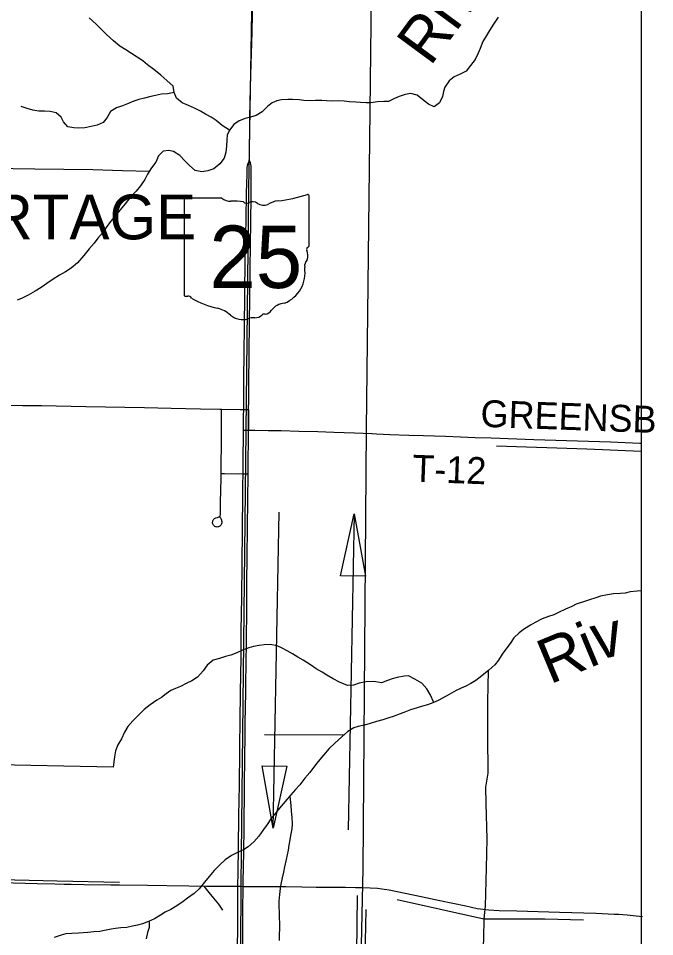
# Model space of a CAD drawing. Extents: x 0 to 680, y 0 to 834.
# Drawn here: x 324.2 to 375.8, y 148.8 to 223.2 of the extents above; entities that cross this region are included whole.
import ezdxf

# ---------------------------------------------------------------- set-up
doc = ezdxf.new("R2010")
doc.units = 0
for name, color, linetype in [('GM_X_Corporation_Text', 7, 'Continuous'), ('GM_X_County_Road', 7, 'Continuous'), ('GM_X_Interstate_Route', 7, 'Continuous'), ('GM_X_Major_River', 7, 'Continuous'), ('GM_X_Minor_River', 7, 'Continuous'), ('GM_X_Minor_River_Text', 7, 'Continuous'), ('GM_X_Rail_Line', 7, 'Continuous'), ('GM_X_State_Location', 7, 'Continuous'), ('GM_X_State_Route', 7, 'Continuous'), ('GM_X_State_Shield', 7, 'Continuous'), ('GM_X_Township_Road', 7, 'Continuous'), ('GM_X_Township_Road_Text', 7, 'Continuous'), ('SH_Text', 7, 'Continuous')]:
    doc.layers.add(name, color=color, linetype=linetype)

msp = doc.modelspace()

# ---------------------------------------------------------------- linework, layer by layer
at = {"layer": 'GM_X_County_Road'}
for p, q in [((342.032, 152.832), (342.242, 152.831)), ((342.242, 152.831), (342.455, 152.828))]:
    msp.add_line(p, q, dxfattribs=at)
for points in [[(310.737, 153.565), (311.451, 153.537), (318.25, 153.307), (319.084, 153.267), (320.873, 153.221), (322.543, 153.165), (323.855, 153.121), (324.809, 153.093), (325.764, 153.069), (327.195, 153.029), (327.935, 153.016), (328.508, 153.006), (329.581, 152.976), (331.728, 152.957), (332.444, 152.957), (334.712, 152.923), (336.263, 152.896), (338.053, 152.879), (339.485, 152.854), (341.274, 152.836), (342.032, 152.832)], [(342.455, 152.828), (343.392, 152.815), (344.704, 152.809), (345.897, 152.808), (347.197, 152.787), (348.37, 152.763), (349.548, 152.761), (350.502, 152.763), (350.74, 152.756), (351.56, 152.745), (351.679, 152.748), (352.152, 152.74), (352.749, 152.72), (353.346, 152.679), (353.703, 152.636), (354.293, 152.534), (356.865, 151.999), (358.382, 151.677), (360.486, 151.236), (361.42, 151.042), (361.889, 150.966), (362.362, 150.917), (363.195, 150.872), (364.626, 150.836), (368.087, 150.74), (371.07, 150.644), (372.517, 150.585)], [(372.517, 150.585), (372.86, 150.571), (373.576, 150.524), (374.051, 150.474), (374.822, 150.37)]]:
    msp.add_lwpolyline(points, dxfattribs=at)
at = {"layer": 'GM_X_Interstate_Route'}
msp.add_lwpolyline([(44.693, 394.069), (374.693, 394.069), (374.693, 64.069), (44.693, 64.069)], close=True, dxfattribs=at)
at = {"layer": 'GM_X_Major_River'}
for points in [[(363.105, 223.315), (362.739, 222.762), (362.402, 222.238), (362.167, 221.83), (361.874, 221.335), (361.669, 220.767), (361.507, 220.388), (361.243, 219.893), (360.863, 219.398), (360.512, 218.933), (360.03, 218.686), (359.563, 218.483)], [(359.563, 218.483), (359.14, 218.149), (358.803, 217.654), (358.685, 217.29), (358.597, 216.896), (358.362, 216.386), (357.938, 216.052), (357.458, 216.272), (356.993, 216.638), (356.543, 216.99), (356.048, 217.123), (355.581, 217.036), (355.1, 216.877), (354.721, 216.718), (354.224, 216.486), (353.86, 216.473), (353.336, 216.46), (352.796, 216.374), (352.432, 216.36), (351.966, 216.391), (351.587, 216.436), (351.077, 216.466), (350.64, 216.511), (350.189, 216.542), (349.722, 216.514), (349.213, 216.545), (348.819, 216.561), (348.309, 216.562), (347.93, 216.549), (347.377, 216.55), (346.984, 216.61), (346.459, 216.655), (346.08, 216.656), (345.57, 216.628), (345.177, 216.528), (344.812, 216.368), (344.447, 216.092), (343.994, 215.641), (343.512, 215.351), (343.045, 215.207), (342.622, 215.106), (342.141, 214.918), (341.703, 214.627), (341.337, 214.162), (341.161, 213.739), (341.116, 213.375), (341.1, 212.864), (341.055, 212.383), (340.922, 211.888), (340.571, 211.422), (340.089, 211.015), (339.593, 210.856), (339.097, 210.785), (338.573, 210.888), (338.108, 211.283), (337.76, 211.649), (337.309, 212.102), (336.8, 212.425), (336.436, 212.499), (335.97, 212.442), (335.605, 212.064), (335.384, 211.554), (335.033, 211.103), (334.697, 210.593), (334.477, 210.142), (334.14, 209.647), (333.774, 209.196), (333.277, 208.673), (332.882, 208.192), (332.487, 207.698), (332.107, 207.232), (331.712, 206.752), (331.361, 206.272), (331.097, 205.893), (330.688, 205.399), (330.366, 204.991), (329.971, 204.526), (329.532, 204.002), (329.021, 203.406), (328.524, 202.955), (328.057, 202.679), (327.575, 202.389), (327.049, 202.07), (326.553, 201.721), (326.086, 201.402), (325.604, 201.111), (325.02, 200.778), (324.495, 200.502), (324.13, 200.357)], [(374.693, 176.786), (374.377, 176.759), (373.823, 176.702), (373.4, 176.601), (373.022, 176.588), (372.468, 176.546), (371.987, 176.474), (371.404, 176.359), (371.039, 176.229), (370.529, 176.07), (370.033, 175.911), (369.449, 175.708), (369.084, 175.535), (368.574, 175.303), (368.005, 175.042), (367.64, 174.853), (367.202, 174.709), (366.692, 174.521), (366.123, 174.23), (365.743, 174.013), (365.261, 173.723), (364.823, 173.388), (364.399, 172.981), (364.092, 172.53), (363.741, 172.064), (363.448, 171.657), (363.155, 171.176), (362.848, 170.783), (362.366, 170.362), (361.796, 169.911), (361.3, 169.534), (360.891, 169.272), (360.497, 169.069), (360.118, 168.895), (359.709, 168.707), (359.14, 168.388), (358.614, 168.083), (358.25, 167.909), (357.826, 167.706), (357.389, 167.547), (356.981, 167.431), (356.543, 167.301), (356.003, 167.142), (355.478, 166.94), (355.099, 166.795), (354.676, 166.636), (354.166, 166.462), (353.772, 166.332), (353.261, 166.188), (352.751, 166.029), (352.284, 165.914), (351.774, 165.798), (351.41, 165.683), (350.928, 165.378), (350.46, 164.956), (349.89, 164.447), (349.423, 163.997), (348.955, 163.473), (348.531, 162.964), (348.238, 162.585), (347.843, 162.061), (347.448, 161.61), (347.039, 161.072)], [(347.039, 161.072), (346.688, 160.693), (346.322, 160.242), (345.869, 159.704), (345.401, 159.166), (345.109, 158.787), (344.684, 158.293), (344.392, 157.856), (344.114, 157.448), (343.719, 156.895), (343.324, 156.429), (342.856, 156.022), (342.491, 155.79), (342.039, 155.602), (341.514, 155.326), (341.003, 154.978), (340.55, 154.57), (340.111, 154.105), (339.702, 153.639), (339.307, 153.159), (338.883, 152.635), (338.488, 152.257), (337.948, 151.865), (337.583, 151.589), (337.087, 151.255), (336.59, 150.95), (336.123, 150.732), (335.759, 150.485), (335.262, 150.181), (334.781, 149.978), (334.299, 149.789), (333.877, 149.674), (333.483, 149.588), (333.031, 149.501), (332.55, 149.474), (332.113, 149.417), (331.749, 149.359), (331.209, 149.244), (330.845, 149.172), (330.364, 149.13), (329.868, 149.088), (329.475, 149.06), (329.096, 149.032), (328.557, 149.004), (328.076, 148.976), (327.697, 148.875), (327.143, 148.687)]]:
    msp.add_lwpolyline(points, dxfattribs=at)
at = {"layer": 'GM_X_Minor_River'}
for points in [[(245.729, 222.703), (245.676, 219.669), (245.678, 215.687), (245.626, 213.106), (247.214, 213.072), (253.915, 212.95), (258.548, 212.805), (262.03, 212.707), (264.535, 212.583), (268.338, 212.499), (275.417, 212.186), (281.885, 211.933), (289.082, 211.634), (294.021, 211.473), (301.086, 211.306), (305.632, 211.249), (314.33, 211.106), (322.037, 211.069), (325.563, 211.029), (330.269, 210.957), (332.687, 210.877), (334.85, 210.826)], [(341.337, 214.162), (340.741, 214.528), (340.276, 214.952), (339.869, 215.201), (339.404, 215.465), (338.996, 215.685), (338.502, 215.935), (338.022, 216.17), (337.512, 216.375), (337.047, 216.741), (336.859, 217.209), (336.774, 217.719), (336.28, 218.187), (335.786, 218.626), (335.204, 219.08), (334.71, 219.461), (334.318, 219.768), (333.852, 220.076), (332.951, 220.662), (332.457, 220.97), (331.933, 221.394), (331.381, 221.907), (330.553, 222.74), (329.987, 223.267)], [(336.859, 217.209), (336.32, 217.108), (335.824, 217.08), (335.343, 216.965), (334.964, 216.893), (334.454, 216.749), (333.987, 216.634), (333.593, 216.504), (333.068, 216.286), (332.674, 216.127), (332.179, 215.968), (331.711, 215.663), (331.433, 215.197), (331.111, 214.775), (330.615, 214.558), (330.134, 214.443), (329.624, 214.342), (329.128, 214.329), (328.72, 214.359), (328.254, 214.434), (327.891, 214.843), (327.703, 215.208), (327.311, 215.56), (326.816, 215.663), (326.364, 215.694), (325.883, 215.695), (325.417, 215.784), (324.952, 215.917), (324.457, 216.064)], [(362.978, 188.561), (370.306, 188.306), (374.693, 188.122)], [(357.915, 167.748), (357.596, 168.392), (357.335, 168.86), (356.943, 169.313), (356.361, 169.636), (355.852, 169.9), (355.488, 169.886), (354.934, 169.771), (354.525, 169.656), (354.146, 169.525), (353.665, 169.337), (353.039, 169.441), (352.427, 169.428), (351.858, 169.299), (351.391, 169.154), (350.896, 169.126), (350.27, 169.376), (349.747, 169.655), (349.238, 169.948), (348.845, 170.212), (348.38, 170.476), (347.915, 170.783), (347.304, 171.179), (346.882, 171.428), (346.46, 171.692), (346.024, 171.926), (345.602, 172.146), (345.195, 172.323), (344.642, 172.455), (344.161, 172.428), (343.738, 172.371), (343.301, 172.284), (342.922, 172.169), (342.411, 171.995), (341.93, 171.778), (341.463, 171.575), (341.025, 171.46), (340.544, 171.301), (340.034, 171.171), (339.537, 170.778), (339.215, 170.313), (338.762, 169.804), (338.295, 169.499), (337.886, 169.31), (337.375, 169.034), (336.982, 168.875), (336.602, 168.701), (336.223, 168.44), (335.828, 168.135), (335.449, 167.932), (334.908, 167.554), (334.441, 167.176), (333.973, 166.725), (333.506, 166.26), (333.096, 165.78), (332.833, 165.328), (332.583, 164.804), (332.29, 164.294), (332.114, 163.814), (332.04, 163.332), (331.907, 162.501)], [(362.295, 170.306), (362.241, 167.81), (362.262, 165.053), (362.281, 162.019), (362.103, 160.867), (362.128, 159.54), (362.192, 156.695), (362.155, 154.303), (362.058, 151.211), (361.953, 150.19), (361.934, 148.63), (361.776, 144.765), (361.527, 139.412), (361.412, 135.284), (361.448, 132.599)], [(350.621, 165.102), (344.181, 165.12)], [(331.907, 162.501), (310.564, 162.914), (304.528, 156.791)], [(346.238, 160.143), (346.305, 159.382), (346.347, 158.915), (346.404, 158.448), (346.417, 157.908), (346.387, 157.5), (346.283, 156.961), (346.224, 156.596), (346.149, 156.173), (346.09, 155.75), (346.03, 155.386), (345.942, 155.007), (345.809, 154.424), (345.72, 153.986), (345.602, 153.52), (345.499, 153.01), (345.439, 152.645), (345.394, 152.164), (345.349, 151.639), (345.347, 151.143), (345.36, 150.764), (345.373, 150.239), (345.387, 149.874), (345.382, 148.444)], [(312.953, 153.732), (316.726, 153.59), (321.65, 153.415), (327.375, 153.281), (332.445, 153.165)], [(339.262, 152.838), (339.669, 152.341), (340.061, 151.859), (340.453, 151.391), (340.772, 150.894)], [(351.702, 152.087), (351.629, 147.405), (351.52, 135.385), (351.483, 128.033), (351.356, 119.966), (351.26, 111.987), (351.21, 105.174), (351.169, 101.104), (351.114, 92.789), (351.127, 87.435), (351.104, 84.488), (351.101, 78.551), (351.032, 75.196), (350.922, 67.479), (350.857, 64.069)], [(354.921, 151.757), (361.953, 150.19), (364.576, 150.197), (366.907, 150.191), (370.024, 150.109)], [(352.398, 150.962), (352.346, 148.366), (352.318, 143.917), (352.278, 140.255), (352.237, 136.39), (352.122, 132.276), (352.142, 129.14), (352.046, 126.252), (352.004, 122.065), (352.003, 117.047), (351.907, 114.173), (351.898, 111.153), (351.871, 107.113), (351.831, 103.524), (351.79, 99.337), (351.749, 95.457), (351.733, 90.074), (351.75, 86.12)], [(334.824, 149.963), (334.823, 149.496), (334.705, 149.074), (334.587, 148.563)]]:
    msp.add_lwpolyline(points, dxfattribs=at)
at = {"layer": 'GM_X_Rail_Line'}
for points in [[(351.218, 64.069), (351.448, 90.121), (351.798, 116.184), (351.86, 139.423), (352.175, 154.252), (352.451, 189.912), (352.901, 229.863), (353.003, 247.107), (353.355, 298.069), (353.602, 311.675), (353.78, 316.856), (353.954, 319.076), (354.473, 323.516), (355.976, 338.772), (356.265, 341.847), (356.561, 344.985), (356.644, 347.076), (356.685, 349.146), (356.788, 357.395), (356.901, 372.817), (357.146, 391.252), (357.174, 394.069)], [(341.694, 64.069), (341.887, 75.733), (342.297, 152.995), (342.913, 209.384), (343.255, 230.188), (343.597, 251.334), (344.253, 291.298), (344.078, 319.736), (344.92, 358.256)]]:
    msp.add_lwpolyline(points, dxfattribs=at)
at = {"layer": 'GM_X_State_Route'}
for p, q in [((342.735, 209.079), (342.768, 210.568)), ((342.768, 210.568), (342.772, 210.721))]:
    msp.add_line(p, q, dxfattribs=at)
for points in [[(343.155, 221.214), (343.18, 222.128), (343.203, 223.559), (343.212, 224.131), (343.215, 224.281)], [(342.955, 211.701), (342.995, 215.175), (343.021, 216.415), (343.083, 218.662), (343.155, 221.214)], [(342.772, 210.721), (342.774, 210.857), (342.789, 211.081), (342.812, 211.284), (342.854, 211.474), (342.955, 211.701)], [(343.097, 210.721), (343.105, 211.069), (343.099, 211.224), (343.075, 211.391), (343.039, 211.498), (342.955, 211.701)], [(343.092, 208.899), (343.095, 209.791), (343.097, 210.721)], [(341.998, 147.653), (342.01, 149.682), (342.027, 151.472), (342.031, 152.785), (342.032, 152.832), (342.056, 153.978), (342.079, 156.007), (342.112, 158.513), (342.121, 159.826), (342.146, 161.019), (342.22, 166.628), (342.227, 168.181), (342.231, 168.538), (342.293, 171.401), (342.3, 173.55), (342.339, 176.295), (342.371, 179.04), (342.391, 181.666), (342.427, 184.649), (342.425, 185.366), (342.441, 186.297), (342.446, 186.559), (342.444, 187.156), (342.476, 189.837), (342.49, 190.975), (342.495, 191.496), (342.519, 193.839), (342.539, 196.226), (342.563, 198.135), (342.613, 203.626), (342.686, 206.864), (342.735, 209.079)], [(342.993, 200.533), (343.017, 202.738), (343.045, 205.007), (343.066, 206.558), (343.092, 208.899)], [(342.897, 191.495), (342.91, 192.234), (342.912, 193.547), (342.972, 198.56), (342.993, 200.533)], [(342.877, 189.831), (342.885, 190.802), (342.897, 191.495)], [(342.418, 147.352), (342.434, 150.814), (342.455, 152.828), (342.458, 153.202), (342.494, 155.589), (342.521, 157.618), (342.549, 160.841), (342.59, 163.467), (342.608, 164.9), (342.624, 165.973), (342.641, 167.406), (342.666, 168.48), (342.68, 169.554), (342.706, 170.628), (342.747, 175.164), (342.763, 177.552), (342.785, 179.461), (342.804, 181.968), (342.845, 186.286), (342.854, 187.221), (342.872, 189.13), (342.877, 189.831)]]:
    msp.add_lwpolyline(points, dxfattribs=at)
at = {"layer": 'GM_X_State_Shield'}
for p, q in [((340.729, 208.631), (337.764, 208.631)), ((347.789, 204.802), (347.789, 208.821)), ((337.664, 208.499), (337.664, 200.814)), ((347.788, 204.803), (347.789, 204.802))]:
    msp.add_line(p, q, dxfattribs=at)
for centre, radius, start, end in [((337.78, 208.515), 0.117, 98.1301, 188.1301), ((341.435, 209.523), 1.138, 231.61951, 271.11188), ((344.182, 219.108), 10.737, 275.84447, 288.90645), ((347.677, 208.838), 0.113, 351.86209, 97.738), ((341.812, 204.317), 4.084, 80.48669, 94.98827), ((342.74, 208.555), 0.328, 219.79206, 297.10237), ((343.221, 207.667), 0.682, 54.46668, 119.14113), ((344.102, 208.885), 0.821, 233.85621, 294.82819), ((345.552, 206.284), 2.16, 97.34618, 120.76885), ((347.763, 204.506), 0.174, 107.94398, 210.33697), ((346.653, 203.998), 1.047, 340.03296, 23.64957), ((347.669, 204.786), 0.121, 289.60381, 7.73413), ((348.193, 203.119), 0.762, 136.8065, 186.92959), ((344.784, 202.608), 2.686, 292.30889, 8.98584), ((337.781, 200.797), 0.118, 171.95839, 258.30661), ((337.799, 201.584), 0.903, 267.33899, 280.60386), ((337.984, 200.371), 0.326, 29.74838, 93.27175), ((342.095, 207.275), 7.754, 240.41292, 257.1985), ((339.783, 197.362), 2.426, 47.18416, 75.83597), ((345.916, 198.657), 1.471, 94.40312, 142.57675), ((342.407, 200.333), 1.539, 230.70037, 286.29184), ((343.297, 197.676), 1.265, 85.69512, 111.20995), ((343.409, 199.757), 0.82, 268.77702, 315.54927), ((344.151, 199.013), 0.231, 65.75173, 132.64842), ((344.053, 200.069), 0.868, 282.87319, 323.27711)]:
    msp.add_arc(centre, radius, start, end, dxfattribs=at)
at = {"layer": 'GM_X_Township_Road'}
for p, q in [((342.692, 191.496), (342.897, 191.495)), ((342.476, 189.837), (342.686, 189.834)), ((342.686, 189.834), (342.877, 189.831)), ((342.645, 186.292), (342.845, 186.286))]:
    msp.add_line(p, q, dxfattribs=at)
for points in [[(322.534, 191.875), (324.562, 191.838), (326.113, 191.821), (329.693, 191.751), (334.466, 191.667), (336.613, 191.621), (337.806, 191.59), (338.999, 191.562), (340.55, 191.533), (340.71, 191.528)], [(340.67, 186.3), (340.676, 186.674), (340.681, 187.463), (340.686, 188.285), (340.688, 188.711), (340.695, 189.299), (340.698, 189.419), (340.702, 190.161), (340.706, 190.742), (340.708, 191.216), (340.71, 191.528)], [(340.71, 191.528), (342.2, 191.498), (342.495, 191.496)], [(342.495, 191.496), (342.652, 191.496), (342.692, 191.496)], [(342.897, 191.495), (342.885, 190.802), (342.877, 189.831)], [(342.877, 189.831), (343.402, 189.824), (344.47, 189.8), (345.54, 189.79), (346.964, 189.755), (348.507, 189.706), (349.809, 189.669), (351.47, 189.616), (352.18, 189.576), (352.87, 189.547)], [(352.87, 189.547), (352.897, 189.547), (353.253, 189.531), (354.327, 189.482), (355.878, 189.428), (357.071, 189.401), (358.86, 189.328), (360.054, 189.291), (361.246, 189.24), (362.559, 189.194), (366.019, 189.082), (370.434, 188.944), (372.223, 188.874), (374.609, 188.784), (374.693, 188.78)], [(340.621, 183.467), (340.624, 184.042), (340.646, 184.88), (340.652, 185.265), (340.657, 185.598), (340.666, 186.074), (340.67, 186.3)], [(340.67, 186.3), (340.929, 186.3), (342.035, 186.297), (342.404, 186.299), (342.441, 186.297)], [(342.441, 186.297), (342.527, 186.295), (342.645, 186.292)], [(340.551, 182.813), (340.598, 182.756), (340.628, 182.71), (340.652, 182.667), (340.679, 182.596), (340.695, 182.53), (340.707, 182.468), (340.714, 182.404), (340.712, 182.315), (340.696, 182.236), (340.677, 182.181), (340.653, 182.127), (340.616, 182.081), (340.571, 182.043), (340.518, 182.012), (340.462, 181.99), (340.406, 181.977), (340.343, 181.97), (340.275, 181.974), (340.226, 181.985), (340.169, 182.01), (340.122, 182.039), (340.077, 182.081), (340.042, 182.127), (340.014, 182.181), (339.994, 182.237), (339.981, 182.296), (339.979, 182.357), (339.985, 182.419), (339.998, 182.475), (340.022, 182.531), (340.051, 182.58), (340.095, 182.623), (340.138, 182.658), (340.191, 182.684), (340.247, 182.708), (340.364, 182.743), (340.477, 182.784), (340.511, 182.805), (340.538, 182.824), (340.569, 182.858), (340.6, 182.909), (340.615, 182.965), (340.618, 183.084), (340.621, 183.467)]]:
    msp.add_lwpolyline(points, dxfattribs=at)
at = {"layer": 'SH_Text'}
for p, q in [((344.896, 157.545), (345.371, 183.167)), ((351.444, 183.031), (350.968, 157.409))]:
    msp.add_line(p, q, dxfattribs=at)
for points in [[(350.342, 178.01), (351.444, 183.031), (352.358, 177.973)], [(345.997, 162.566), (344.896, 157.545), (343.981, 162.603)]]:
    msp.add_lwpolyline(points, close=True, dxfattribs=at)

# ---------------------------------------------------------------- texts
at = {"layer": 'GM_X_Corporation_Text'}
msp.add_text('PORTAGE', height=3.6364, rotation=0.00001, dxfattribs=at).set_placement((314.869, 205.302))
at = {"layer": 'GM_X_Minor_River_Text'}
for s, height, rotation, p in [('River', 3.6383, 53.62845, (357.614, 219.268)), ('Ri', 3.6384, 22.57794, (367.297, 169.182)), ('v', 3.638, 12.57929, (371.084, 171.154))]:
    msp.add_text(s, height=height, rotation=rotation, dxfattribs=at).set_placement(p)
at = {"layer": 'GM_X_State_Location'}
for s in ['s', 'r']:
    msp.add_text(s, height=0.00727, dxfattribs=at).set_placement((343.172, 220.568))
msp.add_text('25', height=0.00727, rotation=0.00001, dxfattribs=at).set_placement((341.341, 220.039))
at = {"layer": 'GM_X_State_Shield'}
msp.add_text('25', height=5.0625, dxfattribs=at).set_placement((339.711, 201.356))
at = {"layer": 'GM_X_Township_Road_Text'}
for s, rotation, p in [('GREENSB', 357.95443, (361.66, 190.103)), ('T-12', 357.88157, (356.127, 185.653))]:
    msp.add_text(s, height=2.1818, rotation=rotation, dxfattribs=at).set_placement(p)

doc.saveas('drawing.dxf')
